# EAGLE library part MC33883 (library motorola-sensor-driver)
Full Bridge Pre-Driver 55V Source: www.motorola.com/... MC33883.pdf
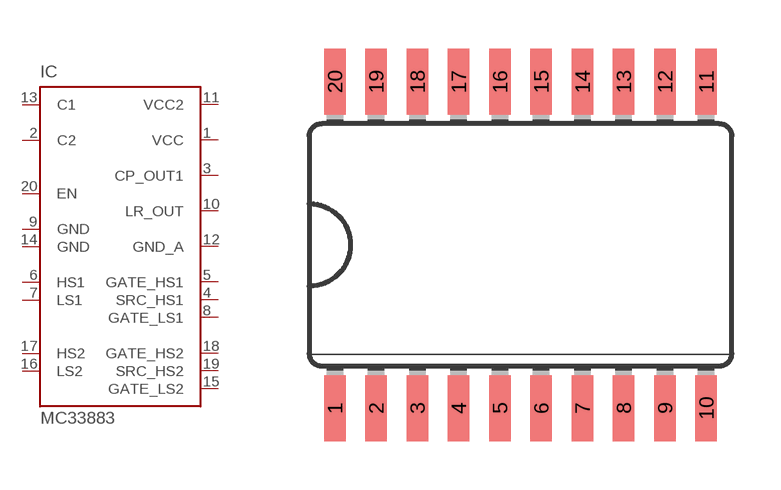
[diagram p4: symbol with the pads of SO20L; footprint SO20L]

Designator prefix IC

## MC33883DW  [SO20L]
1  VCC  pwr
2  C2  pas
3  CP_OUT1  pas
4  SRC_HS1  out
5  GATE_HS1  out
6  HS1  in
7  LS1  in
8  GATE_LS1  out
9  GND  pwr
10  LR_OUT  pas
11  VCC2  pwr
12  GND_A  pwr
13  C1  pas
14  GND  pwr
15  GATE_LS2  out
16  LS2  in
17  HS2  in
18  GATE_HS2  out
19  SRC_HS2  out
20  EN  in

## Footprint SO20L (pad centres in mm)
Small Outline Package
smd 0.66 x 2.032: 1 -5.715,-5.029; 2 -4.445,-5.029; 3 -3.175,-5.029; 4 -1.905,-5.029; 5 -0.635,-5.029; 6 0.635,-5.029; 7 1.905,-5.029; 8 3.175,-5.029; 9 4.445,-5.029; 10 5.715,-5.029; 11 5.715,5.029; 12 4.445,5.029; 13 3.175,5.029; 14 1.905,5.029; 15 0.635,5.029; 16 -0.635,5.029; 17 -1.905,5.029; 18 -3.175,5.029; 19 -4.445,5.029; 20 -5.715,5.029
